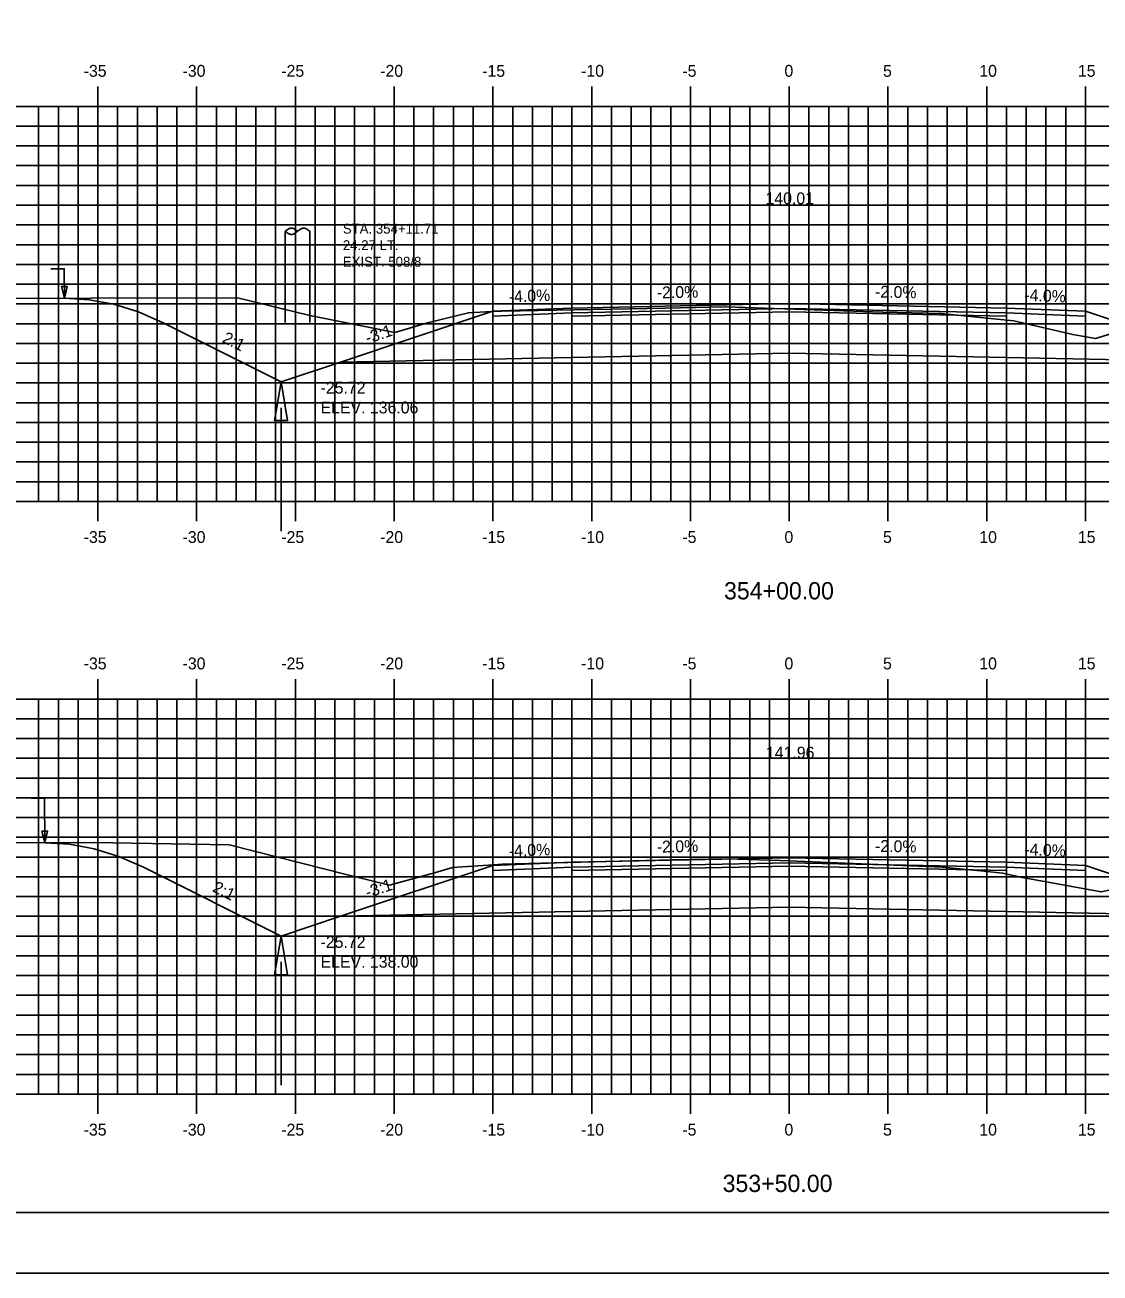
# Model space of a CAD drawing. Extents: x 1145194 to 1145364, y 608981 to 609091.
# Drawn here: x 1145238.4 to 1145292.9, y 608981.3 to 609044.5 of the extents above; entities that cross this region are included whole.
import ezdxf

# ---------------------------------------------------------------- set-up
doc = ezdxf.new("R2010")
doc.units = 0
for name, color, linetype in [('ANNOTATION', 7, 'Continuous'), ('BORDER', 7, 'Continuous'), ('D_Drainage_Ditch_Line', 7, 'Continuous'), ('D_Roadway_Centerline', 7, 'Continuous'), ('D_Roadway_Centerline_Text', 7, 'Continuous'), ('D_Roadway_Edge_Shoulder', 7, 'Continuous'), ('D_Roadway_Edge_TW', 7, 'Continuous'), ('D_Roadway_Pavement', 7, 'Continuous'), ('D_Roadway_SlopeLines', 7, 'Continuous'), ('D_Roadway_SubGrade', 7, 'Continuous'), ('D_Text_Monospaced', 7, 'Continuous'), ('D_Text_Standard', 7, 'Continuous'), ('H_V ANNOTATION', 7, 'Continuous'), ('MAJOR', 7, 'Continuous'), ('MINOR', 7, 'Continuous'), ('PLOT BOUNDARY', 7, 'Continuous'), ('S_Roadway_Centerline', 7, 'Continuous'), ('S_Utilities_Pole_Power', 7, 'Continuous')]:
    doc.layers.add(name, color=color, linetype=linetype)

msp = doc.modelspace()

# ---------------------------------------------------------------- linework, layer by layer
for points in [[(1145240.436, 609030.623), (1145241.686, 609030.548), (1145242.936, 609030.316), (1145244.186, 609029.927), (1145245.436, 609029.38), (1145251.407, 609026.395), (1145254.407, 609027.395), (1145262.131, 609029.969), (1145262.132, 609029.969), (1145266.132, 609030.129), (1145277.132, 609030.349), (1145288.132, 609030.129), (1145292.132, 609029.969), (1145299.855, 609027.395), (1145302.855, 609026.395), (1145309.682, 609029.808), (1145310.932, 609030.361), (1145312.182, 609030.769), (1145313.432, 609031.033), (1145314.682, 609031.153)], [(1145239.447, 609003.059), (1145240.697, 609002.984), (1145241.947, 609002.751), (1145243.197, 609002.362), (1145244.447, 609001.816), (1145251.407, 608998.336), (1145254.407, 608999.336), (1145262.131, 609001.91), (1145262.132, 609001.91), (1145266.132, 609002.07), (1145277.132, 609002.29), (1145288.132, 609002.07), (1145292.132, 609001.91), (1145299.855, 608999.336), (1145302.855, 608998.336), (1145308.513, 609001.164), (1145309.763, 609001.716), (1145311.013, 609002.121), (1145312.263, 609002.379), (1145313.513, 609002.49)]]:
    msp.add_lwpolyline(points)
at = {"layer": 'BORDER'}
msp.add_lwpolyline([(1145202.132, 608984.335), (1145362.132, 608984.335), (1145362.132, 609089.335), (1145202.132, 609089.335)], close=True, dxfattribs=at)
at = {"layer": 'D_Drainage_Ditch_Line'}
for p, q in [((1145251.407, 609025.082), (1145251.407, 609018.839)), ((1145251.407, 608997.023), (1145251.407, 608990.78))]:
    msp.add_line(p, q, dxfattribs=at)
for points in [[(1145251.735, 609024.426), (1145251.079, 609024.426), (1145251.407, 609026.395)], [(1145251.735, 608996.367), (1145251.079, 608996.367), (1145251.407, 608998.336)]]:
    msp.add_lwpolyline(points, close=True, dxfattribs=at)
at = {"layer": 'D_Roadway_Edge_Shoulder'}
for points in [[(1145266.132, 609030.129), (1145262.132, 609029.969), (1145262.132, 609029.719), (1145266.132, 609029.879)], [(1145288.132, 609030.129), (1145292.132, 609029.969), (1145292.132, 609029.719), (1145288.132, 609029.879)], [(1145266.132, 609002.07), (1145262.132, 609001.91), (1145262.132, 609001.66), (1145266.132, 609001.82)], [(1145288.132, 609002.07), (1145292.132, 609001.91), (1145292.132, 609001.66), (1145288.132, 609001.82)]]:
    msp.add_lwpolyline(points, close=True, dxfattribs=at)
at = {"layer": 'D_Roadway_Edge_TW'}
for points in [[(1145266.132, 609029.879), (1145266.132, 609030.129), (1145277.132, 609030.349), (1145288.132, 609030.129), (1145288.132, 609029.879), (1145277.132, 609030.099)], [(1145266.132, 609001.82), (1145266.132, 609002.07), (1145277.132, 609002.29), (1145288.132, 609002.07), (1145288.132, 609001.82), (1145277.132, 609002.04)]]:
    msp.add_lwpolyline(points, close=True, dxfattribs=at)
at = {"layer": 'D_Roadway_Pavement'}
for points in [[(1145266.132, 609029.712), (1145266.132, 609029.879), (1145277.132, 609030.099), (1145288.132, 609029.879), (1145288.132, 609029.712), (1145277.132, 609029.932)], [(1145266.132, 609001.653), (1145266.132, 609001.82), (1145277.132, 609002.04), (1145288.132, 609001.82), (1145288.132, 609001.653), (1145277.132, 609001.873)]]:
    msp.add_lwpolyline(points, close=True, dxfattribs=at)
at = {"layer": 'D_Roadway_SlopeLines'}
for points in [[(1145251.407, 609026.395), (1145245.436, 609029.38), (1145244.186, 609029.927), (1145242.936, 609030.316), (1145241.686, 609030.548), (1145240.436, 609030.623)], [(1145254.407, 609027.395), (1145251.407, 609026.395)], [(1145251.407, 608998.336), (1145244.447, 609001.816), (1145243.197, 609002.362), (1145241.947, 609002.751), (1145240.697, 609002.984), (1145239.447, 609003.059)], [(1145254.407, 608999.336), (1145251.407, 608998.336)]]:
    msp.add_lwpolyline(points, dxfattribs=at)
at = {"layer": 'D_Roadway_SubGrade'}
for points in [[(1145266.132, 609029.712), (1145266.132, 609029.879), (1145262.132, 609029.719), (1145262.132, 609029.969), (1145262.131, 609029.969), (1145254.407, 609027.395), (1145266.132, 609027.629)], [(1145266.132, 609027.629), (1145266.132, 609029.712), (1145277.132, 609029.932), (1145288.132, 609029.712), (1145288.132, 609027.629), (1145277.132, 609027.849)], [(1145288.132, 609029.712), (1145288.132, 609029.879), (1145292.132, 609029.719), (1145292.132, 609029.969), (1145292.132, 609029.969), (1145299.855, 609027.395), (1145288.132, 609027.629)], [(1145266.132, 609001.653), (1145266.132, 609001.82), (1145262.132, 609001.66), (1145262.132, 609001.91), (1145262.131, 609001.91), (1145254.407, 608999.336), (1145266.132, 608999.57)], [(1145266.132, 608999.57), (1145266.132, 609001.653), (1145277.132, 609001.873), (1145288.132, 609001.653), (1145288.132, 608999.57), (1145277.132, 608999.79)], [(1145288.132, 609001.653), (1145288.132, 609001.82), (1145292.132, 609001.66), (1145292.132, 609001.91), (1145292.132, 609001.91), (1145299.855, 608999.336), (1145288.132, 608999.57)]]:
    msp.add_lwpolyline(points, close=True, dxfattribs=at)
at = {"layer": 'D_Text_Standard'}
for points in [[(1145240.436, 609030.63), (1145240.429, 609032.119), (1145239.749, 609032.119)], [(1145239.447, 609003.066), (1145239.427, 609005.313), (1145238.747, 609005.313)]]:
    msp.add_lwpolyline(points, dxfattribs=at)
for points in [[(1145240.436, 609030.63), (1145240.287, 609031.212), (1145240.578, 609031.213)], [(1145239.447, 609003.066), (1145239.296, 609003.646), (1145239.587, 609003.649)]]:
    msp.add_lwpolyline(points, close=True, dxfattribs=at)
at = {"layer": 'MAJOR'}
for p, q in [((1145242.132, 609041.337), (1145242.132, 609040.335)), ((1145247.132, 609041.337), (1145247.132, 609040.335)), ((1145252.132, 609041.337), (1145252.132, 609040.335)), ((1145257.132, 609041.337), (1145257.132, 609040.335)), ((1145262.132, 609041.337), (1145262.132, 609040.335)), ((1145267.132, 609041.337), (1145267.132, 609040.335)), ((1145272.132, 609041.337), (1145272.132, 609040.335)), ((1145277.132, 609041.337), (1145277.132, 609040.335)), ((1145282.132, 609041.337), (1145282.132, 609040.335)), ((1145287.132, 609041.337), (1145287.132, 609040.335)), ((1145292.132, 609041.337), (1145292.132, 609040.335)), ((1145207.132, 609040.335), (1145347.132, 609040.335)), ((1145207.132, 609040.335), (1145347.132, 609040.335)), ((1145242.132, 609020.335), (1145242.132, 609040.335)), ((1145247.132, 609020.335), (1145247.132, 609040.335)), ((1145252.132, 609020.335), (1145252.132, 609040.335)), ((1145257.132, 609020.335), (1145257.132, 609040.335)), ((1145262.132, 609020.335), (1145262.132, 609040.335)), ((1145267.132, 609020.335), (1145267.132, 609040.335)), ((1145272.132, 609020.335), (1145272.132, 609040.335)), ((1145277.132, 609020.335), (1145277.132, 609040.335)), ((1145282.132, 609020.335), (1145282.132, 609040.335)), ((1145287.132, 609020.335), (1145287.132, 609040.335)), ((1145292.132, 609020.335), (1145292.132, 609040.335)), ((1145207.132, 609035.335), (1145347.132, 609035.335)), ((1145207.132, 609030.335), (1145347.132, 609030.335)), ((1145207.132, 609025.335), (1145347.132, 609025.335)), ((1145207.132, 609020.335), (1145347.132, 609020.335)), ((1145207.132, 609020.335), (1145347.132, 609020.335)), ((1145242.132, 609019.333), (1145242.132, 609020.335)), ((1145247.132, 609019.333), (1145247.132, 609020.335)), ((1145252.132, 609019.333), (1145252.132, 609020.335)), ((1145257.132, 609019.333), (1145257.132, 609020.335)), ((1145262.132, 609019.333), (1145262.132, 609020.335)), ((1145267.132, 609019.333), (1145267.132, 609020.335)), ((1145272.132, 609019.333), (1145272.132, 609020.335)), ((1145277.132, 609019.333), (1145277.132, 609020.335)), ((1145282.132, 609019.333), (1145282.132, 609020.335)), ((1145287.132, 609019.333), (1145287.132, 609020.335)), ((1145292.132, 609019.333), (1145292.132, 609020.335)), ((1145242.132, 609011.337), (1145242.132, 609010.335)), ((1145247.132, 609011.337), (1145247.132, 609010.335)), ((1145252.132, 609011.337), (1145252.132, 609010.335)), ((1145257.132, 609011.337), (1145257.132, 609010.335)), ((1145262.132, 609011.337), (1145262.132, 609010.335)), ((1145267.132, 609011.337), (1145267.132, 609010.335)), ((1145272.132, 609011.337), (1145272.132, 609010.335)), ((1145277.132, 609011.337), (1145277.132, 609010.335)), ((1145282.132, 609011.337), (1145282.132, 609010.335)), ((1145287.132, 609011.337), (1145287.132, 609010.335)), ((1145292.132, 609011.337), (1145292.132, 609010.335)), ((1145207.132, 609010.335), (1145347.132, 609010.335)), ((1145207.132, 609010.335), (1145347.132, 609010.335)), ((1145242.132, 608990.335), (1145242.132, 609010.335)), ((1145247.132, 608990.335), (1145247.132, 609010.335)), ((1145252.132, 608990.335), (1145252.132, 609010.335)), ((1145257.132, 608990.335), (1145257.132, 609010.335)), ((1145262.132, 608990.335), (1145262.132, 609010.335)), ((1145267.132, 608990.335), (1145267.132, 609010.335)), ((1145272.132, 608990.335), (1145272.132, 609010.335)), ((1145277.132, 608990.335), (1145277.132, 609010.335)), ((1145282.132, 608990.335), (1145282.132, 609010.335)), ((1145287.132, 608990.335), (1145287.132, 609010.335)), ((1145292.132, 608990.335), (1145292.132, 609010.335)), ((1145207.132, 609005.335), (1145347.132, 609005.335)), ((1145207.132, 609000.335), (1145347.132, 609000.335)), ((1145207.132, 608995.335), (1145347.132, 608995.335)), ((1145207.132, 608990.335), (1145347.132, 608990.335)), ((1145207.132, 608990.335), (1145347.132, 608990.335)), ((1145242.132, 608989.333), (1145242.132, 608990.335)), ((1145247.132, 608989.333), (1145247.132, 608990.335)), ((1145252.132, 608989.333), (1145252.132, 608990.335)), ((1145257.132, 608989.333), (1145257.132, 608990.335)), ((1145262.132, 608989.333), (1145262.132, 608990.335)), ((1145267.132, 608989.333), (1145267.132, 608990.335)), ((1145272.132, 608989.333), (1145272.132, 608990.335)), ((1145277.132, 608989.333), (1145277.132, 608990.335)), ((1145282.132, 608989.333), (1145282.132, 608990.335)), ((1145287.132, 608989.333), (1145287.132, 608990.335)), ((1145292.132, 608989.333), (1145292.132, 608990.335))]:
    msp.add_line(p, q, dxfattribs=at)
at = {"layer": 'MINOR'}
for p, q in [((1145239.132, 609020.335), (1145239.132, 609040.335)), ((1145240.132, 609020.335), (1145240.132, 609040.335)), ((1145241.132, 609020.335), (1145241.132, 609040.335)), ((1145243.132, 609020.335), (1145243.132, 609040.335)), ((1145244.132, 609020.335), (1145244.132, 609040.335)), ((1145245.132, 609020.335), (1145245.132, 609040.335)), ((1145246.132, 609020.335), (1145246.132, 609040.335)), ((1145248.132, 609020.335), (1145248.132, 609040.335)), ((1145249.132, 609020.335), (1145249.132, 609040.335)), ((1145250.132, 609020.335), (1145250.132, 609040.335)), ((1145251.132, 609020.335), (1145251.132, 609040.335)), ((1145253.132, 609020.335), (1145253.132, 609040.335)), ((1145254.132, 609020.335), (1145254.132, 609040.335)), ((1145255.132, 609020.335), (1145255.132, 609040.335)), ((1145256.132, 609020.335), (1145256.132, 609040.335)), ((1145258.132, 609020.335), (1145258.132, 609040.335)), ((1145259.132, 609020.335), (1145259.132, 609040.335)), ((1145260.132, 609020.335), (1145260.132, 609040.335)), ((1145261.132, 609020.335), (1145261.132, 609040.335)), ((1145263.132, 609020.335), (1145263.132, 609040.335)), ((1145264.132, 609020.335), (1145264.132, 609040.335)), ((1145265.132, 609020.335), (1145265.132, 609040.335)), ((1145266.132, 609020.335), (1145266.132, 609040.335)), ((1145268.132, 609020.335), (1145268.132, 609040.335)), ((1145269.132, 609020.335), (1145269.132, 609040.335)), ((1145270.132, 609020.335), (1145270.132, 609040.335)), ((1145271.132, 609020.335), (1145271.132, 609040.335)), ((1145273.132, 609020.335), (1145273.132, 609040.335)), ((1145274.132, 609020.335), (1145274.132, 609040.335)), ((1145275.132, 609020.335), (1145275.132, 609040.335)), ((1145276.132, 609020.335), (1145276.132, 609040.335)), ((1145278.132, 609020.335), (1145278.132, 609040.335)), ((1145279.132, 609020.335), (1145279.132, 609040.335)), ((1145280.132, 609020.335), (1145280.132, 609040.335)), ((1145281.132, 609020.335), (1145281.132, 609040.335)), ((1145283.132, 609020.335), (1145283.132, 609040.335)), ((1145284.132, 609020.335), (1145284.132, 609040.335)), ((1145285.132, 609020.335), (1145285.132, 609040.335)), ((1145286.132, 609020.335), (1145286.132, 609040.335)), ((1145288.132, 609020.335), (1145288.132, 609040.335)), ((1145289.132, 609020.335), (1145289.132, 609040.335)), ((1145290.132, 609020.335), (1145290.132, 609040.335)), ((1145291.132, 609020.335), (1145291.132, 609040.335)), ((1145207.132, 609039.335), (1145347.132, 609039.335)), ((1145207.132, 609038.335), (1145347.132, 609038.335)), ((1145207.132, 609037.335), (1145347.132, 609037.335)), ((1145207.132, 609036.335), (1145347.132, 609036.335)), ((1145207.132, 609034.335), (1145347.132, 609034.335)), ((1145207.132, 609033.335), (1145347.132, 609033.335)), ((1145207.132, 609032.335), (1145347.132, 609032.335)), ((1145207.132, 609031.335), (1145347.132, 609031.335)), ((1145207.132, 609029.335), (1145347.132, 609029.335)), ((1145207.132, 609028.335), (1145347.132, 609028.335)), ((1145207.132, 609027.335), (1145347.132, 609027.335)), ((1145207.132, 609026.335), (1145347.132, 609026.335)), ((1145207.132, 609024.335), (1145347.132, 609024.335)), ((1145207.132, 609023.335), (1145347.132, 609023.335)), ((1145207.132, 609022.335), (1145347.132, 609022.335)), ((1145207.132, 609021.335), (1145347.132, 609021.335)), ((1145239.132, 608990.335), (1145239.132, 609010.335)), ((1145240.132, 608990.335), (1145240.132, 609010.335)), ((1145241.132, 608990.335), (1145241.132, 609010.335)), ((1145243.132, 608990.335), (1145243.132, 609010.335)), ((1145244.132, 608990.335), (1145244.132, 609010.335)), ((1145245.132, 608990.335), (1145245.132, 609010.335)), ((1145246.132, 608990.335), (1145246.132, 609010.335)), ((1145248.132, 608990.335), (1145248.132, 609010.335)), ((1145249.132, 608990.335), (1145249.132, 609010.335)), ((1145250.132, 608990.335), (1145250.132, 609010.335)), ((1145251.132, 608990.335), (1145251.132, 609010.335)), ((1145253.132, 608990.335), (1145253.132, 609010.335)), ((1145254.132, 608990.335), (1145254.132, 609010.335)), ((1145255.132, 608990.335), (1145255.132, 609010.335)), ((1145256.132, 608990.335), (1145256.132, 609010.335)), ((1145258.132, 608990.335), (1145258.132, 609010.335)), ((1145259.132, 608990.335), (1145259.132, 609010.335)), ((1145260.132, 608990.335), (1145260.132, 609010.335)), ((1145261.132, 608990.335), (1145261.132, 609010.335)), ((1145263.132, 608990.335), (1145263.132, 609010.335)), ((1145264.132, 608990.335), (1145264.132, 609010.335)), ((1145265.132, 608990.335), (1145265.132, 609010.335)), ((1145266.132, 608990.335), (1145266.132, 609010.335)), ((1145268.132, 608990.335), (1145268.132, 609010.335)), ((1145269.132, 608990.335), (1145269.132, 609010.335)), ((1145270.132, 608990.335), (1145270.132, 609010.335)), ((1145271.132, 608990.335), (1145271.132, 609010.335)), ((1145273.132, 608990.335), (1145273.132, 609010.335)), ((1145274.132, 608990.335), (1145274.132, 609010.335)), ((1145275.132, 608990.335), (1145275.132, 609010.335)), ((1145276.132, 608990.335), (1145276.132, 609010.335)), ((1145278.132, 608990.335), (1145278.132, 609010.335)), ((1145279.132, 608990.335), (1145279.132, 609010.335)), ((1145280.132, 608990.335), (1145280.132, 609010.335)), ((1145281.132, 608990.335), (1145281.132, 609010.335)), ((1145283.132, 608990.335), (1145283.132, 609010.335)), ((1145284.132, 608990.335), (1145284.132, 609010.335)), ((1145285.132, 608990.335), (1145285.132, 609010.335)), ((1145286.132, 608990.335), (1145286.132, 609010.335)), ((1145288.132, 608990.335), (1145288.132, 609010.335)), ((1145289.132, 608990.335), (1145289.132, 609010.335)), ((1145290.132, 608990.335), (1145290.132, 609010.335)), ((1145291.132, 608990.335), (1145291.132, 609010.335)), ((1145207.132, 609009.335), (1145347.132, 609009.335)), ((1145207.132, 609008.335), (1145347.132, 609008.335)), ((1145207.132, 609007.335), (1145347.132, 609007.335)), ((1145207.132, 609006.335), (1145347.132, 609006.335)), ((1145207.132, 609004.335), (1145347.132, 609004.335)), ((1145207.132, 609003.335), (1145347.132, 609003.335)), ((1145207.132, 609002.335), (1145347.132, 609002.335)), ((1145207.132, 609001.335), (1145347.132, 609001.335)), ((1145207.132, 608999.335), (1145347.132, 608999.335)), ((1145207.132, 608998.335), (1145347.132, 608998.335)), ((1145207.132, 608997.335), (1145347.132, 608997.335)), ((1145207.132, 608996.335), (1145347.132, 608996.335)), ((1145207.132, 608994.335), (1145347.132, 608994.335)), ((1145207.132, 608993.335), (1145347.132, 608993.335)), ((1145207.132, 608992.335), (1145347.132, 608992.335)), ((1145207.132, 608991.335), (1145347.132, 608991.335))]:
    msp.add_line(p, q, dxfattribs=at)
at = {"layer": 'PLOT BOUNDARY'}
msp.add_lwpolyline([(1145194.039, 608981.276), (1145364.039, 608981.276), (1145364.039, 609091.276), (1145194.039, 609091.276)], close=True, dxfattribs=at)
at = {"layer": 'S_Roadway_Centerline'}
for points in [[(1145224.528, 609030.772), (1145234.304, 609030.604), (1145249.208, 609030.65), (1145252.864, 609029.757), (1145257.166, 609028.889), (1145258.819, 609029.378), (1145260.888, 609029.886), (1145261.776, 609029.943), (1145262.584, 609029.963), (1145270.874, 609030.127), (1145273.9, 609030.196), (1145281.879, 609029.922), (1145284.812, 609029.858), (1145287.669, 609029.57), (1145288.499, 609029.477), (1145291.49, 609028.782), (1145292.645, 609028.588), (1145294.997, 609029.318), (1145299.578, 609030.541), (1145307.466, 609030.879), (1145323.345, 609031.482)], [(1145223.166, 609003.006), (1145241.903, 609003.066), (1145248.778, 609002.948), (1145254.838, 609001.419), (1145256.893, 609000.916), (1145259.182, 609001.542), (1145260.082, 609001.809), (1145262.139, 609001.946), (1145262.599, 609001.976), (1145271.221, 609002.19), (1145273.977, 609002.245), (1145276.689, 609002.152), (1145284.89, 609001.824), (1145287.007, 609001.621), (1145287.938, 609001.527), (1145288.943, 609001.294), (1145292.925, 609000.571), (1145297.727, 609001.626), (1145299.356, 609002.061), (1145320.182, 609002.692), (1145322.779, 609002.793)]]:
    msp.add_lwpolyline(points, dxfattribs=at)
at = {"layer": 'S_Utilities_Pole_Power'}
for p, q in [((1145251.616, 609034.015), (1145251.772, 609034.125)), ((1145252.085, 609034.125), (1145252.241, 609034.015)), ((1145252.398, 609034.125), (1145252.241, 609034.015)), ((1145252.866, 609034.015), (1145252.71, 609034.125)), ((1145251.616, 609029.396), (1145251.619, 609034.015)), ((1145251.772, 609033.904), (1145251.616, 609034.015)), ((1145252.241, 609034.015), (1145252.085, 609033.904)), ((1145252.866, 609029.396), (1145252.869, 609034.015))]:
    msp.add_line(p, q, dxfattribs=at)
for centre, start, end in [((1145251.929, 609033.904), 90, 125.26439), ((1145251.929, 609033.904), 54.73561, 90), ((1145252.554, 609033.904), 90, 125.26439), ((1145252.554, 609033.904), 54.73561, 90), ((1145251.929, 609034.125), 234.73561, 270), ((1145251.929, 609034.125), 270, 305.26439)]:
    msp.add_arc(centre, 0.271, start, end, dxfattribs=at)

# ---------------------------------------------------------------- texts
at = {"layer": 'ANNOTATION'}
for s, rotation, p in [('-4.0%', 2.29061, (1145262.948, 609030.403)), ('-2.0%', 1.14576, (1145270.435, 609030.615)), ('-2.0%', 358.85424, (1145281.475, 609030.662)), ('-4.0%', 357.70939, (1145289.028, 609030.494)), ('-3:1', 18.43482, (1145255.786, 609028.308)), ('2:1', 333.43495, (1145248.389, 609028.422)), ('-2.0%', 1.14576, (1145270.435, 609002.556)), ('-2.0%', 358.85424, (1145281.475, 609002.603)), ('-4.0%', 2.29061, (1145262.948, 609002.344)), ('-4.0%', 357.70939, (1145289.028, 609002.435)), ('2:1', 333.43495, (1145247.894, 609000.61)), ('-3:1', 18.43482, (1145255.786, 609000.249))]:
    msp.add_text(s, height=0.6, rotation=rotation, dxfattribs=at).set_placement(p)
at = {"layer": 'D_Roadway_Centerline'}
for s, p in [('C', (1145277.127, 609030.349)), ('L', (1145277.132, 609030.342)), ('C', (1145277.127, 609002.29)), ('L', (1145277.132, 609002.283))]:
    msp.add_text(s, height=0.0146, dxfattribs=at).set_placement(p)
at = {"layer": 'D_Roadway_Centerline_Text'}
for s, p in [('140.01', (1145275.933, 609035.381)), ('141.96', (1145275.955, 609007.322))]:
    msp.add_text(s, height=0.6, dxfattribs=at).set_placement(p)
at = {"layer": 'D_Text_Monospaced'}
for s, height, p in [('STA. 354+11.71', 0.49998, (1145254.533, 609033.894)), ('24.27 LT.', 0.5, (1145254.533, 609033.06)), ('EXIST. 508/8', 0.49998, (1145254.533, 609032.22))]:
    msp.add_text(s, height=height, dxfattribs=at).set_placement(p)
at = {"layer": 'D_Text_Standard'}
for s, p in [('-25.72', (1145253.407, 609025.795)), ('ELEV. 136.06', (1145253.407, 609024.793)), ('-25.72', (1145253.407, 608997.736)), ('ELEV. 138.00', (1145253.407, 608996.734))]:
    msp.add_text(s, height=0.6, dxfattribs=at).set_placement(p)
at = {"layer": 'H_V ANNOTATION'}
for s, height, p in [('-35', 0.6, (1145241.412, 609041.835)), ('-30', 0.6, (1145246.42, 609041.835)), ('-25', 0.6, (1145251.417, 609041.835)), ('-20', 0.6, (1145256.425, 609041.835)), ('-15', 0.6, (1145261.589, 609041.835)), ('-10', 0.6, (1145266.597, 609041.835)), ('-5', 0.6, (1145271.723, 609041.835)), ('0', 0.6, (1145276.891, 609041.835)), ('5', 0.6, (1145281.883, 609041.835)), ('10', 0.6, (1145286.757, 609041.835)), ('15', 0.6, (1145291.749, 609041.835)), ('-35', 0.6, (1145241.412, 609018.235)), ('-30', 0.6, (1145246.42, 609018.235)), ('-25', 0.6, (1145251.417, 609018.235)), ('-20', 0.6, (1145256.425, 609018.235)), ('-15', 0.6, (1145261.589, 609018.235)), ('-10', 0.6, (1145266.597, 609018.235)), ('-5', 0.6, (1145271.723, 609018.235)), ('0', 0.6, (1145276.891, 609018.235)), ('5', 0.6, (1145281.883, 609018.235)), ('10', 0.6, (1145286.757, 609018.235)), ('15', 0.6, (1145291.749, 609018.235)), ('354+00.00', 0.875, (1145273.831, 609015.378)), ('-35', 0.6, (1145241.412, 609011.835)), ('-30', 0.6, (1145246.42, 609011.835)), ('-25', 0.6, (1145251.417, 609011.835)), ('-20', 0.6, (1145256.425, 609011.835)), ('-15', 0.6, (1145261.589, 609011.835)), ('-10', 0.6, (1145266.597, 609011.835)), ('-5', 0.6, (1145271.723, 609011.835)), ('0', 0.6, (1145276.891, 609011.835)), ('5', 0.6, (1145281.883, 609011.835)), ('10', 0.6, (1145286.757, 609011.835)), ('15', 0.6, (1145291.749, 609011.835)), ('-35', 0.6, (1145241.412, 608988.235)), ('-30', 0.6, (1145246.42, 608988.235)), ('-25', 0.6, (1145251.417, 608988.235)), ('-20', 0.6, (1145256.425, 608988.235)), ('-15', 0.6, (1145261.589, 608988.235)), ('-10', 0.6, (1145266.597, 608988.235)), ('-5', 0.6, (1145271.723, 608988.235)), ('0', 0.6, (1145276.891, 608988.235)), ('5', 0.6, (1145281.883, 608988.235)), ('10', 0.6, (1145286.757, 608988.235)), ('15', 0.6, (1145291.749, 608988.235)), ('353+50.00', 0.875, (1145273.761, 608985.378))]:
    msp.add_text(s, height=height, dxfattribs=at).set_placement(p)
at = {"layer": 'S_Roadway_Centerline'}
for s, p in [('L', (1145273.892, 609030.188)), ('C', (1145273.895, 609030.196)), ('L', (1145273.968, 609002.237)), ('C', (1145273.971, 609002.245))]:
    msp.add_text(s, height=0.0146, dxfattribs=at).set_placement(p)

doc.saveas('drawing.dxf')
